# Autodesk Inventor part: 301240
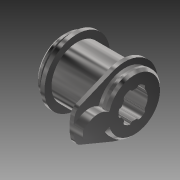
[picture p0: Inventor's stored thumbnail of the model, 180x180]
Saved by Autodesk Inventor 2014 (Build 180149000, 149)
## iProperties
Created: 2007-12
Part Number: 301240
Document SubType Name: Modeling
Designer: TH
Density: 8.08 g/cm^3
Mass: 31.9322 g
Surface Area: 31.3978 cm^2
Volume: 3.95201 cm^3
Material: Stainless Steel
Description: PIVOT CAM BUSHING
Appearance: Steel - Polished
Component Category: Back Component
Author: TH
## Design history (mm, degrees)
sketch "Sketch1"
  geometry: L1 (0, 0)-(0, 9); L2 (0, 9)-(-1.5, 9); L3 (-1.5, 9)-(-1.5, 8); L4 (-1.5, 8)-(-3, 8); L5 (-3, 8)-(-3, 10.5); L6 (-3, 10.5)-(-4.3, 10.5); L7 (-4.3, 10.5)-(-4.3, 8.25); L8 (-4.3, 8.25)-(-18.35, 8.25); L9 (-18.35, 8.25)-(-18.35, 10.5); L10 (-18.35, 10.5)-(-19.65, 10.5); L11 (-19.65, 10.5)-(-19.65, 8); L12 (-19.65, 8)-(-21.15, 8); L13 (-21.15, 8)-(-21.15, 9); L14 (-21.15, 9)-(-22.65, 9); L15 (-22.65, 9)-(-22.65, 0); L16 (-22.65, 0)-(0, 0)
  constraints: 32 end point, 12 parallel, 3 perpendicular, 1 vertical
  dimensions: "d0" = 9 distance of L1.start L1.end; "d1" = 1.5 distance of L1.end L2.end; "d2" = 1.5 distance of L3.end L4.end; "d3" = 1.3 distance of L5.end L6.end; "d4" = 14.05 distance of L7.end L8.end; "d5" = 1.3 distance of L9.end L10.end; "d6" = 1.5 distance of L11.end L12.end; "d7" = 22.65 distance between parallel lines of L1 L15; "d8" = 8 distance between parallel lines of L16 L4; "d9" = 10.5 distance between parallel lines of L16 L6; "d10" = 8.25 distance between parallel lines of L16 L8; "d11" = 10.5 distance between parallel lines of L16 L10; "d12" = 8 distance between parallel lines of L16 L12; "d13" = 9 distance between parallel lines of L16 L14
revolve "Revolution1" sketch "Sketch1" stored, may be unused: angle "d14" = 90 deg
chamfer "Chamfer1" distance "d15" = 0.75; stored, may be unused: second distance "d16" = 2, angle "d17" = 45 deg
chamfer "Chamfer2" distance "d18" = 0.75; stored, may be unused: second distance "d19" = 2, angle "d20" = 30 deg
chamfer "Chamfer3" distance "d21" = 0.75; stored, may be unused: second distance "d22" = 2, angle "d23" = 30 deg
sketch "Sketch2"
  geometry: L1 (-9.701, -4.018)-(-5.405, -14.389); L2 (0, -27.273)-(0, 23.796) reference; L3 (9.701, -4.018)-(5.405, -14.389); C1 r 8.75 at (0, 0) reference; C2 r 8 at (0, 0) reference; A1 r 10.5 centre (0, 0) between (-9.701, -4.018) and (9.701, -4.018) reference; A2 r 16.5 centre (0, 0) between (-3.219, -16.183) and (3.219, -16.183); A3 r 3 centre (-2.633, -13.241) between (-5.405, -14.389) and (-3.219, -16.183); A4 r 3 centre (2.633, -13.241) between (3.219, -16.183) and (5.405, -14.389); A5 r 5.25 centre (-1.976, -11.557) between (2.993, -13.252) and (1.707, -7.816); A6 r 8 centre (0, 0) between (-1.707, -7.816) and (1.707, -7.816); A7 r 5.25 centre (1.976, -11.557) between (-1.707, -7.816) and (-2.993, -13.252); A8 r 9.5 centre (-5.998, -10.186) between (1.134, -16.461) and (2.993, -13.252); A9 r 9.5 centre (5.998, -10.186) between (-2.993, -13.252) and (-1.134, -16.461); 2 further points
  constraints: 20 point on circle, 8 centre point, 7 tangent, 4 coincident, 4 end point, 1 equal radius, 1 symmetric about line
  dimensions: "d24" = 33 diameter of A2; "d25" = 22.5 deg angle of L1 L2; "d26" = 22.5 deg angle of L3 L2 (= d25); "d27" = 3 radius of A3; "d28" = 5.99844 horizontal distance of A1.centre point (-5.998, -10.186); "d29" = 5.99844 horizontal distance of point (5.998, -10.186) A1.centre; "d30" = 10.18595 vertical distance of A1.centre point (-5.998, -10.186); "d31" = 10.18595 vertical distance of point (5.998, -10.186) A1.centre; "d35" = 11.55748 vertical distance of A1.centre A5.centre; "d36" = 8 radius of A6; "d37" = 5.25 radius of A5; "d38" = 5.25 radius of A7; "d39" = 9.5 radius of A9; "d40" = 9.5 radius of A8
extrude "Extrusion1" join sketch "Sketch2" distance "d41" = 3; taper "d42" = 0 deg
extrude "Extrusion2" join sketch "Sketch2" distance "d43" = 1.3; taper "d44" = 0 deg
fillet "Fillet1" dims "d45" = 0.25
workplane "Work Plane1"
sketch "Sketch4" dims "d0" = 9, "d1" = 1.5, "d2" = 1.5, "d3" = 1.3, "d4" = 14.05, "d5" = 1.3, "d6" = 1.5, "d7" = 22.65, "d8" = 8, "d9" = 10.5, "d10" = 8.25, "d11" = 10.5, "d12" = 8, "d13" = 9
  geometry: L1 (-2.991, 3.32)-(-3.053, 3.356) reference; L2 (-4.433, 0.966)-(-4.371, 0.93) reference; L3 (-4.371, -0.93)-(-4.433, -0.966) reference; L4 (-3.053, -3.356)-(-2.991, -3.32) reference; L5 (-1.38, -4.251)-(-1.38, -4.322) reference; L6 (1.38, -4.322)-(1.38, -4.251) reference; L7 (2.991, -3.32)-(3.053, -3.356) reference; L8 (4.433, -0.966)-(4.371, -0.93) reference; L9 (4.371, 0.93)-(4.433, 0.966) reference; L10 (3.053, 3.356)-(2.991, 3.32) reference; C1 r 8.25 at (0, 0) reference; A1 r 4.29 centre (0, 0) between (2.687, 3.344) and (-2.687, 3.344) reference; A2 r 0.27 centre (-2.856, 3.554) between (-2.991, 3.32) and (-2.687, 3.344) reference; A3 r 0.7 centre (-3.403, 2.75) between (-3.053, 3.356) and (-3.947, 3.19) reference; A4 r 5.075 centre (0, 0) between (-3.947, 3.19) and (-4.736, 1.824) reference; A5 r 0.7 centre (-4.083, 1.572) between (-4.736, 1.824) and (-4.433, 0.966) reference; A6 r 0.27 centre (-4.506, 0.697) between (-4.24, 0.655) and (-4.371, 0.93) reference; A7 r 4.29 centre (0, 0) between (-4.24, 0.655) and (-4.24, -0.655) reference; A8 r 0.27 centre (-4.506, -0.697) between (-4.371, -0.93) and (-4.24, -0.655) reference; A9 r 0.7 centre (-4.083, -1.572) between (-4.433, -0.966) and (-4.736, -1.824) reference; A10 r 5.075 centre (0, 0) between (-4.736, -1.824) and (-3.947, -3.19) reference; A11 r 0.7 centre (-3.403, -2.75) between (-3.947, -3.19) and (-3.053, -3.356) reference; A12 r 0.27 centre (-2.856, -3.554) between (-2.687, -3.344) and (-2.991, -3.32) reference; A13 r 4.29 centre (0, 0) between (-2.687, -3.344) and (-1.552, -3.999) reference; A14 r 0.27 centre (-1.65, -4.251) between (-1.38, -4.251) and (-1.552, -3.999) reference; A15 r 0.7 centre (-0.68, -4.322) between (-1.38, -4.322) and (-0.789, -5.013) reference; A16 r 5.075 centre (0, 0) between (-0.789, -5.013) and (0.789, -5.013) reference; A17 r 0.7 centre (0.68, -4.322) between (0.789, -5.013) and (1.38, -4.322) reference; A18 r 0.27 centre (1.65, -4.251) between (1.552, -3.999) and (1.38, -4.251) reference; A19 r 4.29 centre (0, 0) between (1.552, -3.999) and (2.687, -3.344) reference; A20 r 0.27 centre (2.856, -3.554) between (2.991, -3.32) and (2.687, -3.344) reference; A21 r 0.7 centre (3.403, -2.75) between (3.053, -3.356) and (3.947, -3.19) reference; A22 r 5.075 centre (0, 0) between (3.947, -3.19) and (4.736, -1.824) reference; A23 r 0.7 centre (4.083, -1.572) between (4.736, -1.824) and (4.433, -0.966) reference; A24 r 0.27 centre (4.506, -0.697) between (4.24, -0.655) and (4.371, -0.93) reference; A25 r 4.29 centre (0, 0) between (4.24, -0.655) and (4.24, 0.655) reference; A26 r 0.27 centre (4.506, 0.697) between (4.371, 0.93) and (4.24, 0.655) reference; A27 r 0.7 centre (4.083, 1.572) between (4.433, 0.966) and (4.736, 1.824) reference; A28 r 5.075 centre (0, 0) between (4.736, 1.824) and (3.947, 3.19) reference; A29 r 0.7 centre (3.403, 2.75) between (3.947, 3.19) and (3.053, 3.356) reference; A30 r 0.27 centre (2.856, 3.554) between (2.687, 3.344) and (2.991, 3.32) reference; 1 further point
  constraints: 60 point on circle, 31 centre point, 20 end point, 112 other
extrude "Extrusion3" cut sketch "Sketch4" stored distance "d46" = 1.3; taper "d47" = 0 deg
body "Solid1"
other parameters: "d32" = 19, "d33" = 19, "d34" = 10.5
